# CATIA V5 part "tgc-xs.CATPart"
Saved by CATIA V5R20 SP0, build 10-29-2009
Part number: TGC-XS
Revision: 3
Definition: design
Nomenclature: TGC-XS
Source: made
Description: NOT SPECIFIED
Bounding box of the stored display mesh (mm): x -2.5 to 12.809, y -8.5 to 1.8, z -11 to 1
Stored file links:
  C:\Users\Utente\Desktop\IO LAVORO\3D X SITO CF\X SITO\PLASTICA\TGC-XS\tgc-xs.CATPart
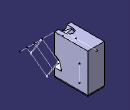
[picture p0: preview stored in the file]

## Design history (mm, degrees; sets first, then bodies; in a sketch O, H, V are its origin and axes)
Set1
  Line1 "COMPOSITE_CURVE #2715": stored without definition
  DatumCurve1 "COMPOSITE_CURVE #2730"
  DatumCurve2 "COMPOSITE_CURVE #2749"
  DatumCurve3 "COMPOSITE_CURVE #2792"
  Line2 "COMPOSITE_CURVE #2799": stored without definition
  DatumCurve4 "COMPOSITE_CURVE #2824"
  Line3 "COMPOSITE_CURVE #2831": stored without definition
  Line4 "LINE #2835": stored without definition
  DatumSurface1 "OPEN_SHELL #2605"
  DatumSurface2 "OPEN_SHELL #2702"
Body1 "MANIFOLD_SOLID_BREP #2703" (main body)
  Solid1: solid without history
